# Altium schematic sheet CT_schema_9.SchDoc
size 278 x 170 mm
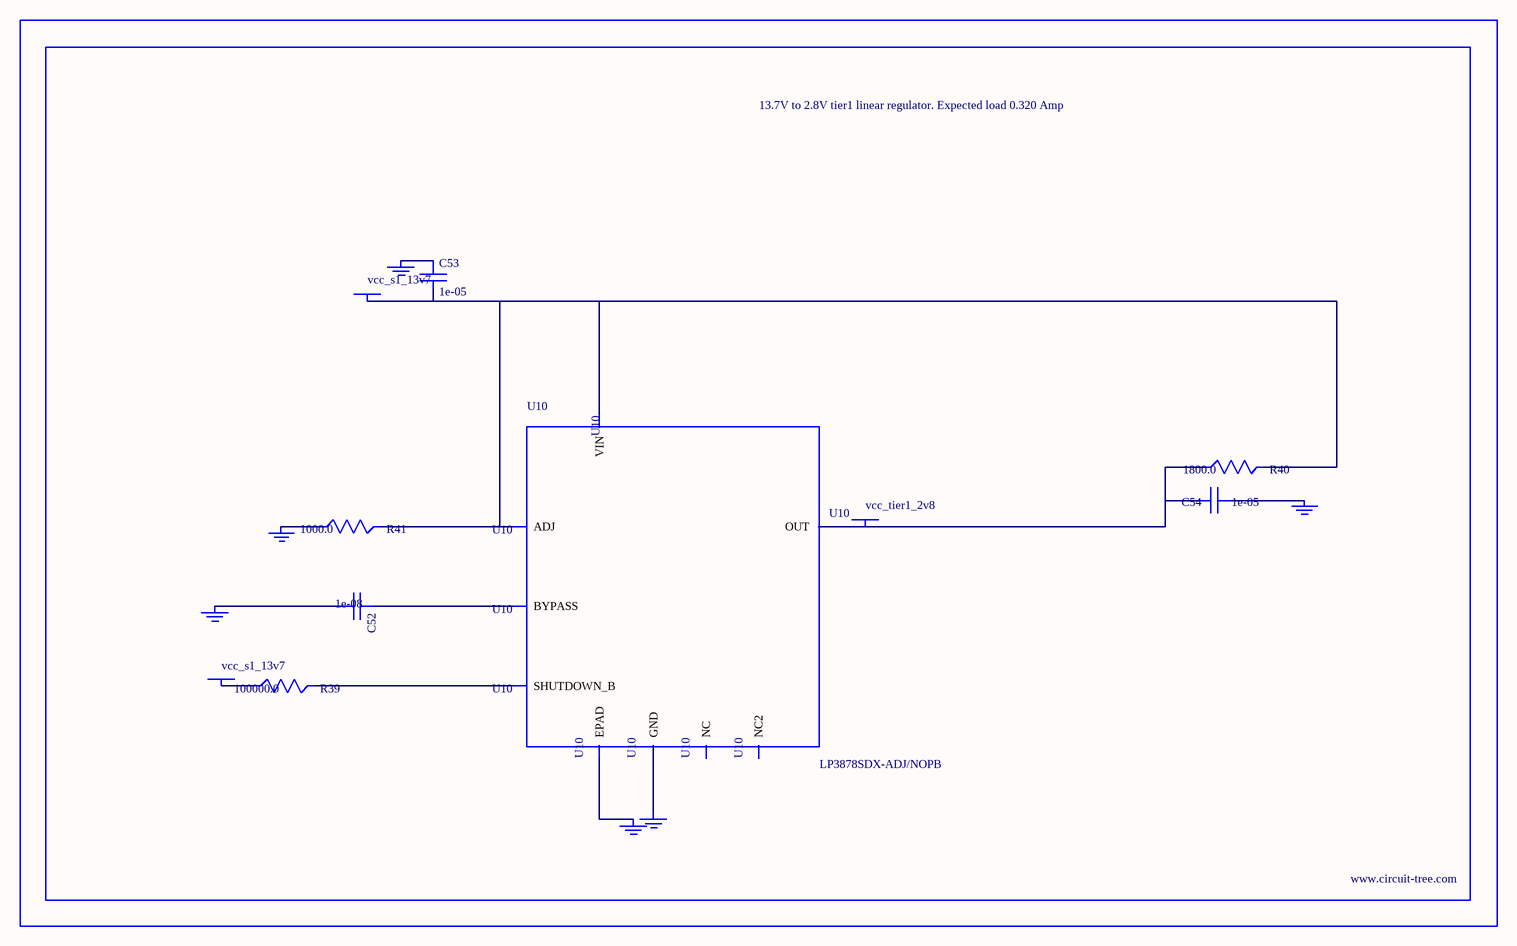
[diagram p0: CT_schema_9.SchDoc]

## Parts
BORDER8  (no value)
C52  1e-08  [C0402]
C53  1e-05  [C1210]
C54  1e-05  [C1210]
GND_INSTANCE_8_0  (no value)
GND_INSTANCE_8_1  (no value)
GND_INSTANCE_8_2  (no value)
GND_INSTANCE_8_3  (no value)
GND_INSTANCE_8_4  (no value)
GND_INSTANCE_8_5  (no value)
POWER_INSTANCE_8_0  vcc_s1_13v7
POWER_INSTANCE_8_1  vcc_s1_13v7
POWER_INSTANCE_8_2  vcc_tier1_2v8
R39  100000.0  [R0603]
R40  1800.0  [R0603]
R41  1000.0  [R0603]
U10  LP3878SDX-ADJ/NOPB  [WSON-8]

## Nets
NetC52_1: C52.1 U10.1(BYPASS)
NetC52_2: C52.2 GND_INSTANCE_8_0.0(GND)
NetC53_1: C53.1 GND_INSTANCE_8_1.0(GND)
NetC53_2: C53.2 POWER_INSTANCE_8_0.0(PWR) R40.2 R41.2 U10.4(VIN) U10.6(ADJ)
NetC54_1: C54.1 GND_INSTANCE_8_2.0(GND)
NetC54_2: C54.2 POWER_INSTANCE_8_2.0(PWR) R40.1 U10.5(OUT)
NetGND_INSTANCE_8_3_0: GND_INSTANCE_8_3.0(GND) R41.1
NetGND_INSTANCE_8_4_0: GND_INSTANCE_8_4.0(GND) U10.PAD(EPAD)
NetGND_INSTANCE_8_5_0: GND_INSTANCE_8_5.0(GND) U10.3(GND)
NetPOWER_INSTANCE_8_1_0: POWER_INSTANCE_8_1.0(PWR) R39.1
NetR39_2: R39.2 U10.8(SHUTDOWN_B)

Not connected (* = marked no-connect by the designer): U10 2(NC) 7(NC2)

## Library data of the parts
BORDER8 = BORDER_PAGE8
C52 = C0402C103K3RAC
C53 = C1210C106K5PACTU
C54 = GRM32DR61E106MA12L
GND_INSTANCE_8_0-GND_INSTANCE_8_5 = GND
POWER_INSTANCE_8_0-POWER_INSTANCE_8_2 = PWR
R39 = RC0603JR-07100KL
R40 = RC0603JR-071K8L
R41 = RC0603JR-071KL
